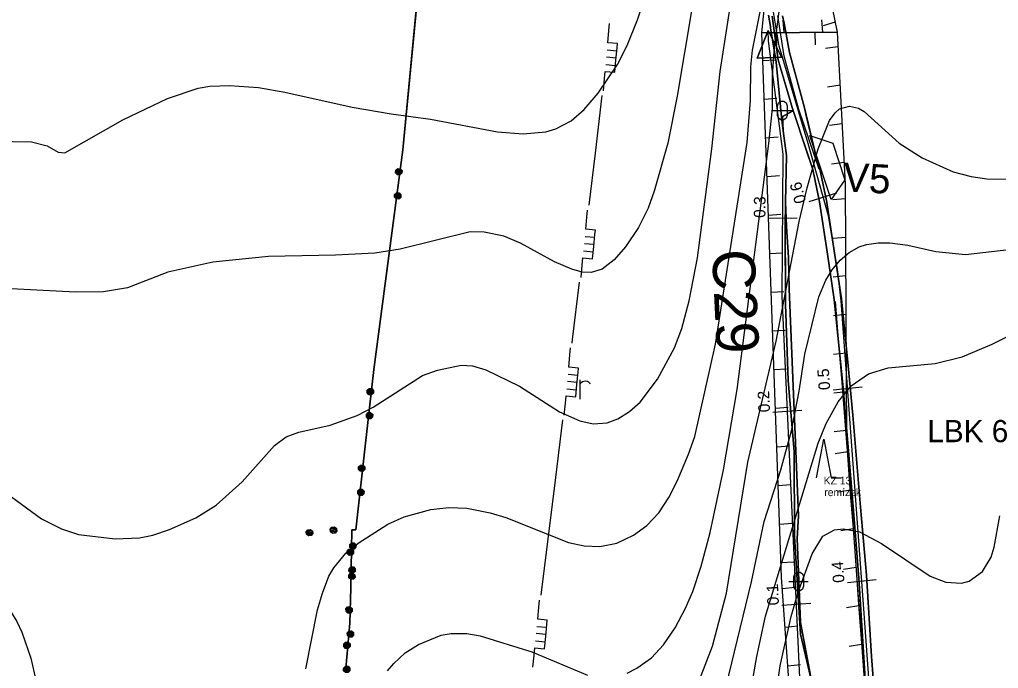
# Model space of a CAD drawing. Extents: x -645676 to -642474, y -1077513 to -1072613.
# Drawn here: x -644532 to -644026, y -1076818 to -1076482 of the extents above; entities that cross this region are included whole.
import ezdxf

# ---------------------------------------------------------------- set-up
doc = ezdxf.new("R2010")
doc.units = 0
for name, color, linetype in [('KRAJ_ZELEN_STAV', 7, 'Continuous'), ('Krajinn__zele____popis___stav', 7, 'Continuous'), ('KULTURY_STAV', 7, 'Continuous'), ('KULTURY_ZNACKY', 7, 'Continuous'), ('Lok_ln__biokoridor___st_vaj_c_', 7, 'Continuous'), ('OBVOD_PU', 7, 'Continuous'), ('Odvodnen__cesty_pod_lnou_dren_____navr_en_', 7, 'Continuous'), ('PC_NAVRH', 7, 'Continuous'), ('PC_OBJ_POPIS_NAVRH', 7, 'Continuous'), ('PC_OBJEKTY_NAVRH', 7, 'Continuous'), ('PC_POPIS_NAVRH', 7, 'Continuous'), ('PC_STAN_NAVRH', 7, 'Continuous'), ('PLYNOVOD', 7, 'Continuous'), ('SPRAV_HR_STAV', 7, 'Continuous'), ('USES_BK_NAVRH', 7, 'Continuous'), ('USES_BK_STAV', 7, 'Continuous'), ('VRSTEVNICE', 7, 'Continuous')]:
    doc.layers.add(name, color=color, linetype=linetype)

# ---------------------------------------------------------------- blocks, each defined once
blk = doc.blocks.new('$944')
blk.add_line((0, 1.5), (0, -1.5))
blk = doc.blocks.new('$920')
for points in [[(0, 0), (-2.8, 1.25), (-2.8, -1.25), (0, 0)], [(-2.8, 1.25), (0, 0), (-2.8, -1.25), (-2.8, 1.25)]]:
    blk.add_lwpolyline(points)
blk = doc.blocks.new('3$0800')
blk.add_lwpolyline([(-0.75, 0), (0, 4), (0.75, 0), (1.75, 0)])
blk = doc.blocks.new('3$1600')
for points in [[(-0.5, 1.5), (-0.4, 1.79), (-0.15, 1.97), (0.16, 1.97), (0.41, 1.79), (0.51, 1.5), (0.51, 0.5), (0.41, 0.21), (0.16, 0.03), (-0.15, 0.03), (-0.4, 0.21), (-0.5, 0.5), (-0.5, 1.5)], [(-1, 1), (0.27, 1), (1, 1)]]:
    blk.add_lwpolyline(points)
blk = doc.blocks.new('$479')
for points in [[(0, 0), (0, 1.27), (0, 2)], [(0, 1.6), (0.1, 1.73), (0.23, 1.84), (0.37, 1.89), (0.6, 1.9), (0.77, 1.87), (0.87, 1.8), (0.96, 1.7), (1, 1.6)]]:
    blk.add_lwpolyline(points)
blk = doc.blocks.new('$925')
for points in [[(-3.5, 0), (-2, 2), (2, 2), (3.5, 0), (-3.5, 0)], [(2, 2), (3.5, 0), (-3.5, 0), (-2, 2), (2, 2)]]:
    blk.add_lwpolyline(points)
blk = doc.blocks.new('2$1030')
blk.add_line((0, 0), (0, -0.5))
blk = doc.blocks.new('6$3520')
for p, q in [((-0.76, 0), (-0.76, -1)), ((0, -1), (0, 0)), ((0.76, 0), (0.76, -1))]:
    blk.add_line(p, q)
blk.add_lwpolyline([(-3.5, 0), (-2.23, 0), (-1.48, 0), (-1.48, -1), (-0.21, -1), (1.06, -1), (1.5, -1), (1.5, 0), (2.77, 0), (3.5, 0)])
blk = doc.blocks.new('2$0620')
for points in [[(-1.07, 0.32), (-0.88, 0.13), (-0.88, -0.14), (-1.07, -0.33), (-1.34, -0.33), (-1.53, -0.14), (-1.53, 0.13), (-1.34, 0.32), (-1.07, 0.32), (-1.08, 0.28), (-1.32, 0.28), (-1.4, 0.2), (-1, 0.2), (-0.92, 0.12), (-1.48, 0.12), (-1.48, 0.04), (-0.92, 0.04), (-0.92, -0.04), (-1.48, -0.04), (-1.48, -0.12), (-0.92, -0.12), (-1, -0.2), (-1.4, -0.2), (-1.32, -0.28), (-1.08, -0.28)], [(1.43, 0.32), (1.62, 0.13), (1.62, -0.14), (1.43, -0.33), (1.16, -0.33), (0.97, -0.14), (0.97, 0.13), (1.16, 0.32), (1.43, 0.32), (1.4, 0.28), (1.16, 0.28), (1.08, 0.2), (1.48, 0.2), (1.56, 0.12), (1, 0.12), (1, 0.04), (1.56, 0.04), (1.56, -0.04), (1, -0.04), (1, -0.12), (1.56, -0.12), (1.48, -0.2), (1.08, -0.2), (1.16, -0.28), (1.4, -0.28)]]:
    blk.add_lwpolyline(points)

msp = doc.modelspace()

# ---------------------------------------------------------------- linework, layer by layer
at = {"layer": 'KRAJ_ZELEN_STAV'}
for points in [[(-644137.6, -1076479.83), (-644133.96, -1076498.84), (-644126.27, -1076527.5), (-644118.7, -1076559.34), (-644129.16, -1076528.42), (-644136.73, -1076500.7), (-644140.1, -1076479.81)], [(-644132.13, -1076529.11), (-644121.9, -1076559.38), (-644118.51, -1076576.09), (-644110.86, -1076626.69), (-644106.19, -1076672.34), (-644101.08, -1076733.84), (-644098.11, -1076770.94), (-644095.57, -1076811.86), (-644092.81, -1076856.03), (-644101.14, -1076855.49), (-644112.73, -1076844.96), (-644122.54, -1076824.87), (-644128.3, -1076799.83), (-644131.39, -1076749.12), (-644131.57, -1076705.27), (-644134.66, -1076668.56), (-644136.14, -1076629.17), (-644136.26, -1076589.23), (-644135.62, -1076552.11), (-644138.15, -1076532.3), (-644132.13, -1076529.11)]]:
    msp.add_lwpolyline(points, dxfattribs=at)
at = {"layer": 'KULTURY_STAV'}
for points in [[(-644363.62, -1076817.66), (-644361.6, -1076794.18), (-644361.11, -1076775.87), (-644360.59, -1076745.94), (-644358.54, -1076745.84), (-644358.2, -1076742.83), (-644353.68, -1076702.62), (-644349.14, -1076663), (-644334.21, -1076549.28), (-644325.14, -1076454.91)], [(-644143.01, -1076480.06), (-644139.88, -1076502.73), (-644138.68, -1076506.8), (-644132.13, -1076529.11), (-644133.45, -1076529.81), (-644137.56, -1076531.99), (-644138.15, -1076532.3), (-644140.97, -1076503.91), (-644143.83, -1076486.15), (-644143.93, -1076485.51), (-644144.9, -1076479.52)], [(-644144.9, -1076479.52), (-644143.93, -1076485.51), (-644143.83, -1076486.15), (-644140.97, -1076503.91), (-644138.15, -1076532.3), (-644137.25, -1076539.37), (-644137.24, -1076539.41), (-644135.62, -1076552.11), (-644136.04, -1076576.29), (-644136.04, -1076576.31), (-644136.26, -1076589.23), (-644136.16, -1076620.88), (-644136.14, -1076629.17), (-644134.66, -1076668.56), (-644131.57, -1076705.27), (-644131.39, -1076749.12), (-644128.3, -1076799.83), (-644122.54, -1076824.87)], [(-644092.81, -1076856.03), (-644095.57, -1076811.86), (-644098.11, -1076770.94), (-644101.08, -1076733.84), (-644106.19, -1076672.34), (-644110.86, -1076626.69), (-644114.6, -1076601.95), (-644118.51, -1076576.09), (-644121.9, -1076559.38), (-644125.69, -1076548.16), (-644131.84, -1076529.97), (-644132.13, -1076529.11), (-644138.68, -1076506.8), (-644139.88, -1076502.73), (-644143.01, -1076480.06)], [(-644137.6, -1076479.83), (-644136.86, -1076483.71), (-644133.96, -1076498.84), (-644126.27, -1076527.5), (-644125.5, -1076530.76), (-644119.7, -1076555.15), (-644118.32, -1076559.23), (-644114.86, -1076575.54), (-644107.18, -1076626.34), (-644104.04, -1076657.44), (-644102.59, -1076671.84), (-644101.32, -1076686.61), (-644097.25, -1076734.09), (-644094.25, -1076769.28), (-644091.62, -1076811.47), (-644088.11, -1076855.97)], [(-644088.11, -1076855.97), (-644091.62, -1076811.47), (-644094.25, -1076769.28), (-644097.25, -1076734.09), (-644101.32, -1076686.61), (-644102.59, -1076671.84), (-644104.04, -1076657.44), (-644107.18, -1076626.34), (-644114.86, -1076575.54), (-644118.32, -1076559.23), (-644119.7, -1076555.15), (-644125.5, -1076530.76), (-644126.27, -1076527.5), (-644133.96, -1076498.84), (-644136.86, -1076483.71), (-644137.6, -1076479.83)], [(-644122.42, -1076824.83), (-644128.33, -1076793.74), (-644130.08, -1076750.28), (-644129.4, -1076738.64), (-644134.12, -1076621.25), (-644134.5, -1076604.98), (-644135.5, -1076588.9), (-644136.04, -1076576.29), (-644135.62, -1076552.11), (-644137.24, -1076539.41), (-644137.25, -1076539.37), (-644137.56, -1076531.99), (-644133.45, -1076529.81), (-644132.13, -1076529.11)], [(-644132.13, -1076529.11), (-644131.84, -1076529.97), (-644125.69, -1076548.16), (-644121.9, -1076559.38), (-644118.51, -1076576.09), (-644114.6, -1076601.95), (-644110.86, -1076626.69), (-644106.19, -1076672.34), (-644101.08, -1076733.84), (-644098.11, -1076770.94), (-644095.57, -1076811.86), (-644092.81, -1076856.03)], [(-644137.56, -1076531.99), (-644137.25, -1076539.37), (-644138.15, -1076532.3), (-644137.56, -1076531.99)], [(-644136.04, -1076576.29), (-644135.5, -1076588.9), (-644134.5, -1076604.98), (-644134.12, -1076621.25), (-644129.4, -1076738.64), (-644130.08, -1076750.28), (-644128.33, -1076793.74), (-644122.42, -1076824.83), (-644122.23, -1076825.5), (-644122.54, -1076824.87), (-644128.3, -1076799.83), (-644131.39, -1076749.12), (-644131.57, -1076705.27), (-644134.66, -1076668.56), (-644136.14, -1076629.17), (-644136.16, -1076620.88), (-644136.26, -1076589.23), (-644136.04, -1076576.31), (-644136.04, -1076576.29)]]:
    msp.add_lwpolyline(points, dxfattribs=at)
at = {"layer": 'OBVOD_PU'}
msp.add_lwpolyline([(-644363.62, -1076817.66), (-644361.6, -1076794.18), (-644361.11, -1076775.87), (-644360.59, -1076745.94), (-644358.54, -1076745.84), (-644358.2, -1076742.83), (-644353.68, -1076702.62), (-644349.14, -1076663), (-644334.21, -1076549.28), (-644325.14, -1076454.91)], dxfattribs=at)
at = {"layer": 'Odvodnen__cesty_pod_lnou_dren_____navr_en_'}
msp.add_lwpolyline([(-644091.16, -1076867.44), (-644092.13, -1076863.91), (-644092.7, -1076858.96), (-644093.47, -1076846.47), (-644094.93, -1076826.58), (-644096.42, -1076806.69), (-644097.88, -1076786.8), (-644099.35, -1076766.81), (-644100.8, -1076747.02), (-644102.38, -1076727.1), (-644103.76, -1076707.24), (-644105.46, -1076687.36), (-644106.97, -1076667.48), (-644108.6, -1076647.62), (-644110.26, -1076627.76)], dxfattribs=at)
at = {"layer": 'PC_NAVRH'}
for points in [[(-643836.45, -1076933.85), (-643871.36, -1076941.32), (-643906.08, -1076948.75), (-643919.35, -1076949.23), (-643944.11, -1076947.99), (-643966.12, -1076947.14), (-644007.95, -1076951.31), (-644029.76, -1076953.02), (-644037.92, -1076952.26), (-644047.69, -1076947.61), (-644055.18, -1076938.88), (-644069.6, -1076907.09), (-644087.24, -1076870.08), (-644090.18, -1076860.69), (-644095.49, -1076786.67), (-644107.26, -1076627.36), (-644109.1, -1076611.08), (-644113.92, -1076583.41), (-644124.28, -1076545.99), (-644139.39, -1076495.57), (-644142.46, -1076477.03)], [(-644126.09, -1076884.28), (-644128.04, -1076837.31), (-644137.84, -1076624.95), (-644137.23, -1076551.5), (-644144.97, -1076492.93), (-644145.06, -1076487.54)]]:
    msp.add_lwpolyline(points, dxfattribs=at)
at = {"layer": 'PLYNOVOD'}
for points in [[(-644237.75, -1076577.96), (-644234.42, -1076550.97), (-644231, -1076521.17)], [(-644246.54, -1076649.31), (-644246.31, -1076647.43), (-644242.64, -1076617.66)], [(-644262.58, -1076779.76), (-644254.91, -1076718.81), (-644251.32, -1076689.03)]]:
    msp.add_lwpolyline(points, dxfattribs=at)
at = {"layer": 'SPRAV_HR_STAV'}
for p, q in [((-644325.14, -1076454.91), (-644334.21, -1076549.28)), ((-644334.21, -1076549.28), (-644349.14, -1076663)), ((-644349.14, -1076663), (-644353.68, -1076702.62)), ((-644353.68, -1076702.62), (-644358.2, -1076742.83)), ((-644358.2, -1076742.83), (-644358.54, -1076745.84)), ((-644360.59, -1076745.94), (-644361.11, -1076775.87)), ((-644358.54, -1076745.84), (-644360.59, -1076745.94)), ((-644361.11, -1076775.87), (-644361.6, -1076794.18)), ((-644361.6, -1076794.18), (-644363.62, -1076817.66))]:
    msp.add_line(p, q, dxfattribs=at)
at = {"layer": 'USES_BK_NAVRH'}
msp.add_lwpolyline([(-644115.99, -1076456.27), (-644109.33, -1076488.41), (-644148.37, -1076488.7), (-644138.52, -1076392.37)], dxfattribs=at)
at = {"layer": 'USES_BK_STAV'}
msp.add_lwpolyline([(-644069.62, -1076948.55), (-644078.66, -1076955.95), (-644083.21, -1076969.09), (-644113.43, -1076963.08), (-644164.73, -1076962.38), (-644200.13, -1076972.62), (-644201.5, -1076971.38), (-644223.26, -1076953.08), (-644157.21, -1076929.58), (-644127.2, -1076896.93), (-644134.31, -1076823.65), (-644138.09, -1076770.36), (-644148.37, -1076488.7), (-644109.33, -1076488.41), (-644105.19, -1076567.03), (-644104.44, -1076698.01), (-644092.5, -1076863.53), (-644061.94, -1076934.44)], close=True, dxfattribs=at)
at = {"layer": 'VRSTEVNICE'}
for points in [[(-644248.33, -1076752.41), (-644240.22, -1076754.15), (-644232.11, -1076754.44), (-644223.43, -1076752.7), (-644214.74, -1076748.65), (-644207.78, -1076743.58), (-644201.7, -1076737.06), (-644196.49, -1076729.09), (-644192.14, -1076720.7), (-644186.21, -1076706.79), (-644183.02, -1076697.52), (-644172.3, -1076649.73), (-644155.94, -1076545.46), (-644154.2, -1076523.74), (-644154.06, -1076506.36), (-644153.19, -1076497.67), (-644147.83, -1076470.73), (-644146.38, -1076443.07)], [(-644547.25, -1076721.13), (-644521.18, -1076740.1), (-644510.75, -1076745.31), (-644502.06, -1076748.21), (-644482.94, -1076750.53), (-644470.49, -1076749.95), (-644463.54, -1076748.65), (-644454.85, -1076745.75), (-644441.24, -1076739.67), (-644430.81, -1076733.15), (-644417.34, -1076720.98), (-644400.54, -1076702.16), (-644394.46, -1076697.81), (-644387.94, -1076695.35), (-644371.72, -1076691.73), (-644357.82, -1076686.66), (-644349.42, -1076682.32), (-644323.93, -1076666.1), (-644316.11, -1076663.2), (-644303.95, -1076660.59), (-644298.15, -1076661.03), (-644291.2, -1076663.05), (-644273.82, -1076671.6), (-644252.97, -1076684.78), (-644242.54, -1076689.56), (-644235.59, -1076691.01), (-644228.35, -1076690.43), (-644222.85, -1076688.4), (-644216.76, -1076684.63), (-644211.26, -1076679.86), (-644202.28, -1076667.98), (-644193.59, -1076651.76), (-644189.68, -1076641.62), (-644185.92, -1076627.43), (-644181.72, -1076605.13), (-644174.19, -1076548.65), (-644169.84, -1076508.68), (-644162.02, -1076457.41)], [(-644546.09, -1076544.74), (-644526.39, -1076545.17), (-644518.28, -1076547.2), (-644512.49, -1076550.38), (-644509.01, -1076550.82), (-644479.03, -1076533.73), (-644456.01, -1076522.72), (-644440.08, -1076517.37), (-644434, -1076516.35), (-644423.86, -1076515.92), (-644408.8, -1076516.93), (-644395.18, -1076519.39), (-644360.43, -1076527.21), (-644340.15, -1076530.69), (-644319.88, -1076533.3), (-644285.12, -1076539.96), (-644271.8, -1076540.97), (-644260.21, -1076539.96), (-644255, -1076538.36), (-644247.03, -1076534.17), (-644240.37, -1076528.37), (-644232.98, -1076519.97), (-644222.99, -1076505.05), (-644218.07, -1076495.35), (-644212.71, -1076482.03), (-644206.92, -1076464.65)], [(-644218.07, -1076820.04), (-644213, -1076817.44), (-644205.47, -1076812.08), (-644199.24, -1076805.41), (-644193.16, -1076796.58), (-644187.8, -1076786.44), (-644184.03, -1076777.75), (-644179.69, -1076764.72), (-644175.05, -1076747.34), (-644168.25, -1076714.9), (-644161.15, -1076673.19), (-644144.64, -1076546.04), (-644142.9, -1076527.79), (-644142.76, -1076510.99), (-644141.75, -1076495.93), (-644137.84, -1076465.95)], [(-644184.61, -1076476.24), (-644192.14, -1076521.42), (-644197.07, -1076545.75), (-644204.02, -1076570.66), (-644207.2, -1076579.35), (-644212.13, -1076589.49), (-644218.94, -1076599.48), (-644224.73, -1076606.14), (-644230.96, -1076610.92), (-644236.75, -1076612.8), (-644241.38, -1076612.51), (-644246.6, -1076611.06), (-644255.58, -1076607.15), (-644273.24, -1076597.6), (-644281.93, -1076593.98), (-644292.07, -1076591.8), (-644299.31, -1076591.66), (-644335.52, -1076600.64), (-644348.55, -1076602.67), (-644368.97, -1076603.82), (-644403.58, -1076604.4), (-644432.55, -1076607.3), (-644455.72, -1076612.51), (-644476.57, -1076620.62), (-644489.03, -1076622.65), (-644503.51, -1076622.94), (-644546.96, -1076620.62)], [(-644180.56, -1076823.52), (-644173.9, -1076806.14), (-644166.65, -1076778.62), (-644155.65, -1076710.85), (-644140.88, -1076648.28), (-644129, -1076586.3), (-644124.95, -1076568.92), (-644119.15, -1076548.65), (-644113.36, -1076534.02), (-644110.46, -1076530.11), (-644108.15, -1076528.08), (-644102.93, -1076526.63), (-644098.3, -1076527.65), (-644095.4, -1076529.39), (-644077.3, -1076545.75), (-644065.43, -1076553.43), (-644049.35, -1076560.67), (-644040.08, -1076563.13), (-644031.97, -1076564.29), (-644017.49, -1076564.43)], [(-644169.7, -1076838.87), (-644153.77, -1076772.83), (-644147.1, -1076741.55), (-644138.56, -1076714.9), (-644133.06, -1076694.63), (-644129, -1076674.06), (-644126.11, -1076654.95), (-644118.86, -1076625.4), (-644115.24, -1076616.71), (-644111.87, -1076611.32), (-644107.86, -1076606.29), (-644103.22, -1076602.38), (-644098.01, -1076599.48), (-644094.24, -1076598.18), (-644088.16, -1076597.31), (-644082.08, -1076597.31), (-644072.81, -1076598.61), (-644058.33, -1076601.8), (-644042.98, -1076603.39), (-644000.98, -1076598.61)], [(-644156.08, -1076840.9), (-644151.01, -1076811.35), (-644146.38, -1076790.5), (-644119.15, -1076701), (-644115.1, -1076690.86), (-644108.87, -1076679.56), (-644102.06, -1076671.31), (-644093.09, -1076665.08), (-644082.95, -1076662.04), (-644058.62, -1076659.87), (-644044.72, -1076656.39), (-644029.08, -1076649.88), (-644008.8, -1076639.59)], [(-644773.46, -1076651.61), (-644761.29, -1076663.49), (-644749.13, -1076677.39), (-644734.79, -1076698.25), (-644717.55, -1076725.33), (-644704.96, -1076737.78), (-644693.95, -1076744.59), (-644683.67, -1076749.22), (-644667.45, -1076753.71), (-644647.17, -1076755.74), (-644611.84, -1076755.74), (-644603.73, -1076756.32), (-644590.69, -1076758.35), (-644582, -1076760.52), (-644569.84, -1076764.72), (-644553.62, -1076773.12), (-644545.22, -1076779.64), (-644537.25, -1076788.04), (-644533.92, -1076793.25), (-644531.31, -1076798.9), (-644526.68, -1076812.22), (-644521.47, -1076835.1), (-644518.14, -1076843.79)], [(-644384.32, -1076817.73), (-644378.24, -1076787.31), (-644375.78, -1076778.62), (-644372.45, -1076769.93), (-644369.84, -1076765.59), (-644363.61, -1076757.91), (-644357.24, -1076752.7), (-644341.89, -1076743), (-644333.49, -1076739.09), (-644319.59, -1076735.32), (-644310.32, -1076734.31), (-644301.05, -1076734.74), (-644288.88, -1076737.06), (-644280.77, -1076739.52), (-644248.33, -1076752.41)], [(-644144.5, -1076855.38), (-644138.85, -1076816.28), (-644133.2, -1076790.79), (-644129.73, -1076778.62), (-644122.34, -1076758.35), (-644116.69, -1076749.08), (-644110.75, -1076745.89), (-644106.12, -1076745.31), (-644097.72, -1076746.91), (-644086.42, -1076752.99), (-644061.23, -1076769.79), (-644053.12, -1076772.98), (-644045.01, -1076773.41), (-644040.95, -1076772.4), (-644034.14, -1076767.47), (-644029.65, -1076759.94), (-644028.06, -1076754.87), (-644025.16, -1076738.65)], [(-644342.03, -1076818.88), (-644338.85, -1076814.97), (-644332.91, -1076809.47), (-644325.96, -1076805.27), (-644314.37, -1076800.35), (-644309.16, -1076799.48), (-644301.05, -1076799.48), (-644294.1, -1076800.64), (-644267.45, -1076809.03), (-644238.49, -1076821.05)]]:
    msp.add_lwpolyline(points, dxfattribs=at)

# ---------------------------------------------------------------- block references
at = {"layer": 'KULTURY_ZNACKY', "xscale": 5, "yscale": 5}
for name, p in [('3$1600', (-644137.71, -1076533.93)), ('$479', (-644242.37, -1076678.32)), ('3$0800', (-644116.25, -1076719.01)), ('3$1600', (-644129.32, -1076777.57))]:
    msp.add_blockref(name, p, dxfattribs=at)
at = {"layer": 'PC_OBJEKTY_NAVRH', "xscale": 5, "yscale": 5, "rotation": -71.552486}
msp.add_blockref('$925', (-644118, -1076558.41), dxfattribs=at)
at = {"layer": 'PC_STAN_NAVRH'}
for name, p, xscale, yscale, rotation in [('$920', (-644145.06, -1076487.54), 5, 5, 92.52123299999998), ('$944', (-644116.62, -1076573.68), 5.000000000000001, 5, 107.316697), ('$944', (-644137.51, -1076584.55), 5, 5, 91.09298599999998), ('$944', (-644103.92, -1076672.67), 5, 4.999999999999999, 95.87324099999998), ('$944', (-644135.09, -1076684.48), 5.000000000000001, 5, 94.25844400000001), ('$944', (-644096.55, -1076772.4), 5, 4.999999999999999, 95.87324099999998), ('$944', (-644130.48, -1076784.38), 5.000000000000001, 5, 94.25844400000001)]:
    msp.add_blockref(name, p, dxfattribs=dict(at, xscale=xscale, yscale=yscale, rotation=rotation))
at = {"layer": 'PLYNOVOD'}
for p, xscale, yscale, rotation in [((-644228.72, -1076501.3), 5.000000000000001, 5, 84.912552), ((-644240.19, -1076597.81), 4.999999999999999, 5.000000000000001, 84.421119), ((-644248.93, -1076669.17), 5, 5, 84.580899), ((-644265.08, -1076799.6), 5, 5, 84.273013)]:
    msp.add_blockref('6$3520', p, dxfattribs=dict(at, xscale=xscale, yscale=yscale, rotation=rotation))
at = {"layer": 'SPRAV_HR_STAV'}
for p, xscale, yscale, rotation in [((-644336.49, -1076566.63), 5, 4.999999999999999, -92.897591), ((-644351.13, -1076680.39), 5, 4.999999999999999, -91.93862899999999), ((-644355.63, -1076720.01), 4.999999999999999, 4.999999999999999, -91.81323400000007), ((-644376.02, -1076746.69), 5, 4.999999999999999, -174.01696000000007), ((-644360.16, -1076760.22), 5, 5.000000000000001, -91.844729), ((-644360.89, -1076763.44), 5.000000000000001, 5, -86.30033200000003), ((-644361.58, -1076793.36), 5, 4.999999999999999, -86.84730600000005), ((-644363.1, -1076811.62), 4.999999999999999, 5, -90.29051000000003)]:
    msp.add_blockref('2$0620', p, dxfattribs=dict(at, xscale=xscale, yscale=yscale, rotation=rotation))
at = {"layer": 'USES_BK_NAVRH', "xscale": 13}
for p, yscale, rotation in [((-644136.83, -1076488.62), 13, -176.41540600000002), ((-644116.83, -1076488.46), 13, -176.41540600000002), ((-644110.41, -1076483.2), 12.999999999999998, -73.37748100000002)]:
    msp.add_blockref('2$1030', p, dxfattribs=dict(at, yscale=yscale, rotation=rotation))
at = {"layer": 'USES_BK_STAV'}
for p, xscale, yscale, rotation in [((-644140.87, -1076488.65), 13, 13.000000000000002, 0.44299899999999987), ((-644120.87, -1076488.49), 13, 13.000000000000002, 0.44299899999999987), ((-644108.93, -1076495.9), 13, 13, -82.22034000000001), ((-644147.85, -1076503.03), 13.000000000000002, 12.999999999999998, 93.69787799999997), ((-644107.88, -1076515.87), 13, 13, -82.22034000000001), ((-644147.12, -1076523.02), 13.000000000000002, 12.999999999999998, 93.69787799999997), ((-644106.83, -1076535.84), 13, 13, -82.22034000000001), ((-644146.39, -1076543.01), 13.000000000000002, 12.999999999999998, 93.69787799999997), ((-644105.78, -1076555.81), 13, 13, -82.22034000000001), ((-644145.66, -1076562.99), 13.000000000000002, 12.999999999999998, 93.69787799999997), ((-644105.15, -1076574.53), 13, 13.000000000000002, -84.95473400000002), ((-644144.93, -1076582.98), 13.000000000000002, 12.999999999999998, 93.69787799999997), ((-644105.03, -1076594.53), 13, 13.000000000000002, -84.95473400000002), ((-644144.2, -1076602.97), 13.000000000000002, 12.999999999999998, 93.69787799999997), ((-644104.92, -1076614.53), 13, 13.000000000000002, -84.95473400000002), ((-644143.47, -1076622.95), 13.000000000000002, 12.999999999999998, 93.69787799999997), ((-644104.8, -1076634.53), 13, 13.000000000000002, -84.95473400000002), ((-644142.74, -1076642.94), 13.000000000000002, 12.999999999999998, 93.69787799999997), ((-644104.69, -1076654.53), 13, 13.000000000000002, -84.95473400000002), ((-644142.01, -1076662.93), 13.000000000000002, 12.999999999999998, 93.69787799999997), ((-644104.57, -1076674.53), 13, 13.000000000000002, -84.95473400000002), ((-644141.28, -1076682.91), 13.000000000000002, 12.999999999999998, 93.69787799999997), ((-644104.46, -1076694.53), 13, 13.000000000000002, -84.95473400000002), ((-644140.55, -1076702.9), 13.000000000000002, 12.999999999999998, 93.69787799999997), ((-644103.9, -1076705.49), 13, 13, -81.09070200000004), ((-644139.82, -1076722.89), 13.000000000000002, 12.999999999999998, 93.69787799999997), ((-644102.46, -1076725.43), 13, 13, -81.09070200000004), ((-644139.09, -1076742.87), 13.000000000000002, 12.999999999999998, 93.69787799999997), ((-644101.02, -1076745.38), 13, 13, -81.09070200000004), ((-644138.36, -1076762.86), 13.000000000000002, 12.999999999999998, 93.69787799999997), ((-644099.58, -1076765.33), 13, 13, -81.09070200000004), ((-644137.67, -1076776.27), 13, 13, 95.701577), ((-644098.15, -1076785.28), 13, 13, -81.09070200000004), ((-644136.25, -1076796.22), 13, 13, 95.701577), ((-644096.71, -1076805.23), 13, 13, -81.09070200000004), ((-644134.84, -1076816.17), 13, 13, 95.701577)]:
    msp.add_blockref('2$1030', p, dxfattribs=dict(at, xscale=xscale, yscale=yscale, rotation=rotation))

# ---------------------------------------------------------------- texts
at = {"layer": 'Krajinn__zele____popis___stav'}
for s, p in [('KZ 13', (-644116.33, -1076722.38)), ('remízek', (-644116.02, -1076728.43))]:
    msp.add_text(s, height=4, dxfattribs=at).set_placement(p)
at = {"layer": 'Lok_ln__biokoridor___st_vaj_c_'}
msp.add_text('LBK 6', height=11.5, dxfattribs=at).set_placement((-644062.68, -1076700.53))
at = {"layer": 'PC_OBJ_POPIS_NAVRH'}
msp.add_text('V5', height=15, rotation=357.078, dxfattribs=at).set_placement((-644106.58, -1076570.76))
at = {"layer": 'PC_POPIS_NAVRH'}
msp.add_text('C29', height=22, rotation=272.728, dxfattribs=at).set_placement((-644174.16, -1076601.2))
at = {"layer": 'PC_STAN_NAVRH'}
for s, rotation, p in [('0.6', 105.482, (-644125.29, -1076576.09)), ('0.3', 89.553, (-644146.5, -1076584.48)), ('0.5', 94.252, (-644112.89, -1076673.34)), ('0.2', 92.647, (-644144.08, -1076684.91)), ('0.4', 94.252, (-644105.52, -1076773.07)), ('0.1', 92.647, (-644139.47, -1076784.8))]:
    msp.add_text(s, height=6, rotation=rotation, dxfattribs=at).set_placement(p)

doc.saveas('drawing.dxf')
